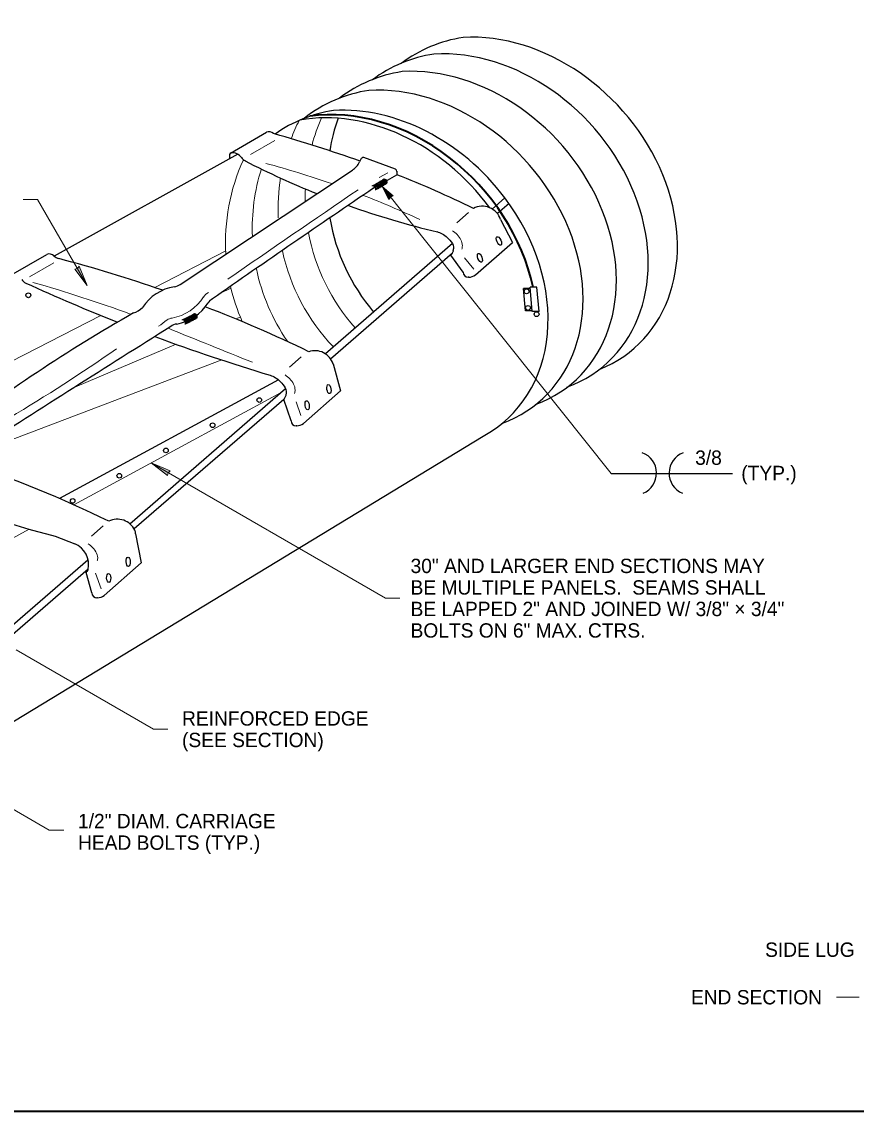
# Model space of a CAD drawing. Extents: x 99860 to 103153, y 99998 to 102077.
# Drawn here: x 100970 to 101901, y 100000 to 101215 of the extents above; entities that cross this region are included whole.
import ezdxf
from ezdxf.enums import TextEntityAlignment as Align

# ---------------------------------------------------------------- set-up
doc = ezdxf.new("R2010")
doc.units = 0
doc.header["$LTSCALE"] = 6.4
for name, color, linetype, lineweight in [('1', 7, 'Continuous', 13), ('15', 7, 'Continuous', 13), ('18', 7, 'Continuous', 25), ('20', 7, 'Continuous', 13), ('6', 7, 'Continuous', 25)]:
    doc.layers.add(name, color=color, linetype=linetype, lineweight=lineweight)

msp = doc.modelspace()

# ---------------------------------------------------------------- hatches: boundary and pattern name
at = {"layer": '15'}
for points in [[(101372.043, 101030.842), (101379.443, 101016.628), (101381.399, 101019.121), (101384.263, 101020.476)], [(101043.153, 100920.663), (101034.323, 100941.926), (101032.266, 100939.519), (101029.153, 100938.941)], [(101114.56, 100722.591), (101132.838, 100708.591), (101133.416, 100711.704), (101135.824, 100713.761)]]:
    msp.add_hatch(color=256, dxfattribs=at).paths.add_polyline_path(points)

# ---------------------------------------------------------------- linework, layer by layer
at = {"layer": '1'}
for p, q in [((101225.31, 101066.683), (101252.49, 101082.453)), ((101378.46, 101046.123), (101368.6, 101040.913)), ((101455.49, 100990.503), (101468.45, 101001.833)), ((101464.04, 100951.583), (101474.52, 100938.883)), ((100978.87, 100930.153), (101006.05, 100945.923)), ((101268.83, 100829.463), (101281.78, 100840.803)), ((101281.4, 100775.373), (101276.03, 100790.683)), ((101047.95, 100641.043), (101060.9, 100652.373)), ((101375.805, 100571.761), (101391.805, 100571.761))]:
    msp.add_line(p, q, dxfattribs=at)
at = {"layer": '1', "lineweight": 35}
msp.add_lwpolyline([(99862, 99999.5), (103151, 99999.5), (103151, 102075.5), (99862, 102075.5)], close=True, dxfattribs=at)
at = {"layer": '1'}
for centre, radius, start, end in [((111586.486, 85956.986), 18220.767, 124.19844, 124.75241), ((100573.08, 99483.351), 1497.731, 69.75334, 74.13445), ((101185.002, 100899.671), 14.559, 117.19844, 147.56246), ((101128.602, 100935.687), 52.352, 280.21474, 327.83323), ((100627.736, 101547.463), 834.945, 306.36128, 307.16981), ((101138.897, 100872.31), 11.898, 94.87554, 124.30163), ((124064.12, 157637.717), 61221.535, 248.00332, 248.09817)]:
    msp.add_arc(centre, radius, start, end, dxfattribs=at)
for points in [[(101450.42, 100981.693), (101455.77, 100977.323), (101461.55, 100964.943), (101461.05, 100960.993)], [(101263.83, 100820.733), (101269.18, 100816.373), (101274.96, 100803.973), (101274.46, 100800.033)]]:
    msp.add_spline(points, degree=3, dxfattribs=at)
at = {"layer": '15'}
for p, q in [((101372.043, 101030.842), (101627.433, 100710.889)), ((100971.774, 101016.58), (100987.774, 101016.58)), ((101043.152, 100920.663), (100987.774, 101016.58)), ((101114.56, 100722.591), (101375.805, 100571.761)), ((100963.784, 100514.003), (101116.884, 100425.611)), ((101116.884, 100425.611), (101132.884, 100425.611)), ((100847.759, 100401.298), (101000.858, 100312.906)), ((101000.858, 100312.906), (101016.858, 100312.906))]:
    msp.add_line(p, q, dxfattribs=at)
for points in [[(101372.043, 101030.842), (101379.443, 101016.628), (101381.399, 101019.121), (101384.263, 101020.476)], [(101043.153, 100920.663), (101034.323, 100941.926), (101032.266, 100939.519), (101029.153, 100938.941)], [(101114.56, 100722.591), (101132.838, 100708.591), (101133.416, 100711.704), (101135.824, 100713.761)]]:
    msp.add_lwpolyline(points, close=True, dxfattribs=at)
at = {"layer": '18'}
for p, q in [((101202.974, 101068.112), (101243.061, 101091.47)), ((101251.869, 101089.755), (101250.925, 101090.094)), ((101210.95, 101067.033), (101006.426, 100953.337)), ((101201.86, 101066.738), (101201.86, 101061.963)), ((101348.81, 101062.103), (101346.98, 101058.303)), ((101386.98, 101050.213), (101351.56, 101063.233)), ((101146.8, 100921.773), (101338.89, 101049.293)), ((101362.4, 101029.083), (101388.39, 101044.083)), ((101388.39, 101048.023), (101388.39, 101044.083)), ((101509.11, 101018.167), (101494.92, 101005.825)), ((101513.65, 101011.933), (101500.69, 101000.664)), ((101504.145, 100994.088), (101517.6, 100968.643)), ((101450.479, 100967.324), (101308.81, 100844.303)), ((101476.13, 100932.453), (101517.6, 100968.643)), ((100957.989, 100932.011), (100997.932, 100955.213)), ((101314.46, 100838.753), (101450.455, 100956.992)), ((101462.54, 100935.343), (101448.87, 100954.373)), ((101468.74, 100929.703), (101468.18, 100929.703)), ((101537.31, 100917.203), (101529.85, 100917.123)), ((101544.77, 100918.603), (101537.31, 100918.533)), ((101539.56, 100891.643), (101537.31, 100918.533)), ((101547.17, 100891.643), (101544.77, 100918.603)), ((101547.17, 100891.643), (101539.7, 100891.493)), ((101317.34, 100833.193), (101325.7, 100802.953)), ((101256.46, 100815.323), (101012.03, 100682.953)), ((101090.59, 100654.833), (101264.28, 100805.643)), ((101284.22, 100766.763), (101325.7, 100802.953)), ((101262.28, 100793.413), (101095.47, 100648.993)), ((101270.63, 100769.653), (101262.28, 100793.413)), ((101276.83, 100764.023), (101276.27, 100764.023)), ((100826.93, 100353.183), (101484.784, 100752.447)), ((101097.09, 100643.713), (101103.45, 100611.093)), ((101007.46, 100640.753), (101029.21, 100632.453)), ((100840.16, 100438.253), (101043.72, 100614.563)), ((101061.97, 100574.903), (101103.45, 100611.093)), ((100847.2, 100433.893), (101044.122, 100604.437)), ((101048.38, 100577.793), (101042.03, 100600.343)), ((101054.58, 100572.163), (101054.01, 100572.163))]:
    msp.add_line(p, q, dxfattribs=at)
at = {"layer": '18', "lineweight": 13}
for p, q in [((101197.64, 100959.033), (101118.45, 100918.233)), ((101203.48, 100917.483), (101191.23, 100911.493)), ((101058.22, 100887.203), (100814.56, 100761.653)), ((101213.857, 100885.342), (101208.846, 100883.218)), ((101142.252, 100854.988), (101029.34, 100807.123)), ((101193.099, 100837.495), (100913.71, 100731.483)), ((101258.643, 100800.749), (101028.27, 100675.783)), ((100700.04, 100497.763), (100978.34, 100648.703)), ((101052.45, 100599.713), (101058.8, 100582.013))]:
    msp.add_line(p, q, dxfattribs=at)
at = {"layer": '18'}
msp.add_lwpolyline([(101539.49, 100892.413), (101532.03, 100892.343), (101529.85, 100917.123)], dxfattribs=at)
for centre, radius in [((100977.464, 100909.638), 2.721), ((101533.235, 100913.97), 2.721), ((101534.827, 100895.519), 2.721), ((101544.395, 100888.535), 2.721), ((101235.017, 100792.814), 2.602), ((101182.989, 100764.67), 2.602), ((101130.963, 100736.533), 2.602), ((101078.94, 100708.393), 2.602), ((101026.91, 100680.243), 2.602)]:
    msp.add_circle(centre, radius, dxfattribs=at)
for centre, radius, start, end in [((101245.842, 101084.206), 7.778, 49.19738, 110.94642), ((100814.265, 99552.685), 1598.149, 70.51099, 74.10834), ((101204.211, 101065.97), 2.473, 101.76903, 161.913), ((101205.261, 101056.841), 11.663, 32.68926, 97.66665), ((101225.671, 101071.222), 13.292, 217.33165, 242.52256), ((101651.897, 101902.563), 947.593, 242.83859, 248.15508), ((101326.727, 101068.232), 22.532, 302.67194, 333.9546), ((101350.861, 101061.087), 2.253, 71.34064, 153.16977), ((101386.119, 101048.07), 2.253, 354.24466, 68.86365), ((101004.122, 100054.897), 1061.214, 63.72573, 68.77282), ((111592.682, 85951.353), 18220.767, 124.1554, 124.84263), ((101651.897, 101902.563), 947.593, 250.42979, 256.70319), ((101483.816, 100987.605), 21.337, 17.68791, 117.79329), ((101000.737, 100947.958), 7.778, 46.85005, 111.13774), ((101016.321, 100964.917), 15.232, 227.59044, 251.21372), ((100650.207, 99558.655), 1437.948, 70.62306, 75.45161), ((101468.177, 100935.337), 5.633, 180, 269.99999), ((100980.707, 100935.116), 13.292, 217.33165, 242.52256), ((101848.722, 102831.009), 2098.428, 245.3816, 248.42173), ((101468.745, 100940.97), 11.266, 270, 311.06982), ((101148.994, 100867.047), 52.847, 99.44318, 146.83874), ((101138.525, 100933.047), 13.986, 277.10171, 306.2885), ((101133.672, 100929.068), 52.352, 280.41252, 327.65579), ((101188.216, 100895.029), 11.9, 117.54866, 149.867), ((101965.069, 99357.739), 1762.081, 119.59772, 127.80756), ((101086.882, 100914.18), 25.55, 287.97692, 314.42411), ((100661.332, 99553.586), 1437.948, 64.06544, 69.07733), ((125612.602, 62046.261), 45899.251, 122.22614, 122.5453), ((101144.034, 100865.607), 12.006, 94.301, 130.47734), ((101844.037, 102812.281), 2079.303, 249.58101, 253.32164), ((101297.031, 100826.507), 21.337, 17.32063, 108.64362), ((101276.269, 100769.651), 5.633, 180, 269.99999), ((101276.837, 100775.284), 11.266, 270, 311.06982), ((100471.719, 99436.706), 1358.332, 63.99523, 71.31279), ((101348.168, 101945.628), 1348.617, 248.453, 255.36636), ((101076.882, 100638.483), 21.337, 25.09429, 116.82179), ((101086.811, 100643.435), 10.281, 0.78483, 23.40469), ((101019.569, 100609.344), 25.039, 347.35659, 67.34315), ((101054.015, 100577.789), 5.633, 180, 269.99999), ((101054.583, 100583.422), 11.266, 270, 311.06982)]:
    msp.add_arc(centre, radius, start, end, dxfattribs=at)
at = {"layer": '18', "lineweight": 13}
for centre, radius, start, end in [((100966.029, 100032.154), 1061.214, 70.77527, 74.91014), ((101361.075, 101028.031), 3.733, 341.29616, 97.67064), ((101361.825, 101028.433), 3.733, 341.29616, 97.67064), ((101362.716, 101028.843), 3.733, 341.29616, 97.67064), ((101363.611, 101029.183), 3.733, 341.29616, 97.67064), ((101364.427, 101029.659), 3.733, 341.29616, 97.67064), ((101365.243, 101030.135), 3.733, 341.29616, 97.67064), ((101365.998, 101030.466), 3.733, 341.29616, 97.67064), ((101366.814, 101030.942), 3.733, 341.29616, 97.67064), ((101367.691, 101031.563), 3.733, 341.29616, 97.67064), ((101368.507, 101032.039), 3.733, 341.29616, 97.67064), ((101369.323, 101032.515), 3.733, 341.29616, 97.67064), ((101370.204, 101033.066), 3.733, 341.29616, 97.67064), ((101371.161, 101033.551), 3.733, 341.29616, 97.67064), ((101371.972, 101034.097), 3.733, 341.29616, 97.67064), ((101372.648, 101034.564), 3.733, 341.29616, 97.67064), ((101373.314, 101035.172), 3.733, 341.29616, 97.67064), ((101374.055, 101035.714), 3.733, 341.29616, 97.67064), ((100966.029, 100032.154), 1061.214, 65.02924, 68.77283), ((101155.574, 100881.731), 3.733, 337.60173, 93.97621), ((101156.419, 100882.154), 3.733, 337.60173, 93.97621), ((101157.264, 100882.576), 3.733, 337.60173, 93.97621), ((101158.179, 100883.069), 3.733, 337.60173, 93.97621), ((101159.165, 100883.491), 3.733, 337.60173, 93.97621), ((101160.01, 100883.984), 3.733, 337.60173, 93.97621), ((101160.714, 100884.407), 3.733, 337.60173, 93.97621), ((101161.418, 100884.97), 3.733, 337.60173, 93.97621), ((101162.193, 100885.463), 3.733, 337.60173, 93.97621), ((101148.744, 100878.633), 3.733, 337.60173, 93.97621), ((101149.519, 100878.985), 3.733, 337.60173, 93.97621), ((101150.434, 100879.337), 3.733, 337.60173, 93.97621), ((101151.349, 100879.619), 3.733, 337.60173, 93.97621), ((101152.194, 100880.041), 3.733, 337.60173, 93.97621), ((101153.039, 100880.464), 3.733, 337.60173, 93.97621), ((101153.814, 100880.745), 3.733, 337.60173, 93.97621), ((101154.659, 100881.168), 3.733, 337.60173, 93.97621), ((100039.702, 102330.132), 1806.839, 300.49804, 304.98269)]:
    msp.add_arc(centre, radius, start, end, dxfattribs=at)
at = {"layer": '18', "lineweight": 40}
msp.add_ellipse((101357.547, 100920.366), major_axis=(-141.602, 153.836), ratio=0.796016, start_param=4.07059976, end_param=5.78595695, dxfattribs=at)
at = {"layer": '18'}
msp.add_ellipse((101370.01, 100925.435), major_axis=(-141.602, 153.836), ratio=0.796016, start_param=2.94377335, end_param=4.58782905, dxfattribs=at)
for centre, major_axis in [((101502.32, 100970.321), (2.127, -4.682)), ((101481.132, 100951.349), (1.845, -4.801)), ((101312.751, 100805.017), (0.777, -5.084)), ((101288.437, 100786.917), (0.777, -5.084)), ((101088.818, 100612.383), (0.176, -5.14)), ((101067.061, 100594.287), (0.176, -5.14))]:
    msp.add_ellipse(centre, major_axis=major_axis, ratio=0.443982, dxfattribs=at)
for points in [[(101433.1, 100980.643), (101435.91, 100979.723), (101447.6, 100971.063), (101451.62, 100963.383), (101451.55, 100962.823)], [(101451.19, 100958.813), (101450.56, 100957.193), (101449.71, 100955.713), (101448.87, 100954.373)], [(101451.55, 100962.823), (101451.48, 100960.783), (101451.12, 100958.813)], [(101247.28, 100820.453), (101250.03, 100819.393), (101261.36, 100810.243), (101265.02, 100802.423), (101264.96, 100801.863)], [(101264.96, 100801.863), (101264.88, 100799.823), (101264.53, 100797.853)], [(101264.6, 100797.853), (101263.97, 100796.233), (101263.13, 100794.753), (101262.28, 100793.413)], [(101044.001, 100603.863), (101043.72, 100603.163), (101042.88, 100601.683), (101042.03, 100600.343)]]:
    msp.add_spline(points, degree=3, dxfattribs=at)
at = {"layer": '18', "lineweight": 13}
msp.add_spline([(101044.07, 100632.523), (101049.21, 100628.013), (101054.7, 100614.983), (101054.35, 100613.443)], degree=3, dxfattribs=at)
at = {"layer": '20', "lineweight": 25}
msp.add_line((101627.433, 100710.889), (101762.775, 100710.889), dxfattribs=at)
at = {"layer": '20'}
msp.add_line((101878.756, 100126.648), (101904.256, 100126.648), dxfattribs=at)
at = {"layer": '20', "lineweight": 25}
for centre, start, end in [((101653.765, 100711.171), 292.76788, 69.54858), ((101716.524, 100711.171), 110.45141, 247.23212)]:
    msp.add_arc(centre, 24.354, start, end, dxfattribs=at)
at = {"layer": '6'}
for centre, radius, start, end in [((101485.467, 101045.749), 153.199, 98.65196, 126.90888), ((101452.867, 101027.231), 153.199, 98.65196, 126.77176), ((101417.379, 101007.656), 153.199, 98.65196, 127.36028), ((101380.201, 100986.744), 153.199, 98.65196, 128.21296), ((101341.193, 100964.423), 153.199, 98.74335, 125.26619), ((101531.778, 101033.57), 221.357, 160.61554, 170.30408), ((101531.778, 101033.57), 221.357, 189.87643, 220.11958)]:
    msp.add_arc(centre, radius, start, end, dxfattribs=at)
at = {"layer": '6', "lineweight": 13}
for centre, start, end in [((101477.35, 101005.335), 153.33798, 159.11337), ((101507.697, 101019.981), 156.71548, 165.01038), ((101418.767, 100969.073), 155.54748, 183.4783), ((101448.551, 100984.211), 162.55826, 182.31688), ((101477.35, 101005.335), 170.86801, 182.41918), ((101507.697, 101019.981), 177.84586, 181.43094), ((101507.697, 101019.981), 190.56916, 221.55052), ((101477.35, 101005.335), 192.01074, 223.83972), ((101448.551, 100984.211), 191.70296, 214.61156), ((101418.767, 100969.073), 192.93104, 203.6321)]:
    msp.add_arc(centre, 221.357, start, end, dxfattribs=at)
at = {"layer": '6'}
for centre, start_param, end_param in [((101514.284, 101006.832), 2.84753997, 5.70624229), ((101481.683, 100988.314), 2.82467208, 5.70624229), ((101446.196, 100968.739), 2.8288998, 5.70624229), ((101409.018, 100947.756), 2.82696128, 5.70624209), ((101351.28, 100916.845), 4.57403964, 5.81394796), ((101370.01, 100925.435), 4.58782905, 5.7074566)]:
    msp.add_ellipse(centre, major_axis=(-141.602, 153.836), ratio=0.796016, start_param=start_param, end_param=end_param, dxfattribs=at)

# ---------------------------------------------------------------- texts
at = {"layer": '20'}
for s, p in [('3/8', (101721.265, 100720.504)), ('(TYP.)', (101772.699, 100703.396)), ('30" AND LARGER END SECTIONS MAY', (101403.805, 100599.761)), ('BE MULTIPLE PANELS.  SEAMS SHALL', (101403.805, 100575.761)), ('BE LAPPED 2" AND JOINED W/ 3/8" × 3/4"', (101403.805, 100551.761)), ('BOLTS ON 6" MAX. CTRS.', (101403.805, 100527.761)), ('REINFORCED EDGE', (101148.884, 100429.611)), ('(SEE SECTION)', (101148.884, 100405.611)), ('1/2" DIAM. CARRIAGE', (101032.851, 100315.11)), ('HEAD BOLTS (TYP.)', (101032.851, 100291.11))]:
    msp.add_text(s, height=16, dxfattribs=at).set_placement(p)
for s, p in [('SIDE LUG', (101899.149, 100171.678)), ('END SECTION', (101862.761, 100118.648))]:
    msp.add_text(s, height=16, dxfattribs=at).set_placement(p, align=Align.RIGHT)

doc.saveas('drawing.dxf')
